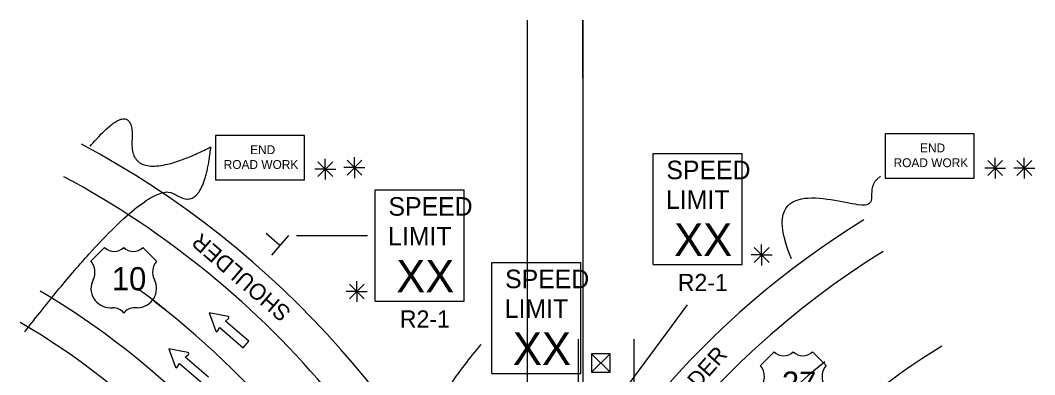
# Model space of a CAD drawing. Extents: x 16284 to 18474, y 5417 to 6974.
# Drawn here: x 16725.7 to 17163.1, y 6821.2 to 6974.1 of the extents above; entities that cross this region are included whole.
import ezdxf

# ---------------------------------------------------------------- set-up
doc = ezdxf.new("R2010")
doc.units = 0
for name, color, linetype in [('ALI_LEGAL_EX', 7, 'Continuous'), ('MT_SCRATCH_LEVEL_E', 7, 'Continuous'), ('PAVT_EDGE_EX', 7, 'Continuous'), ('TRAFFIC_SIGNS_PR', 7, 'Continuous'), ('TYPICAL_EX', 7, 'Continuous'), ('TYPICAL_TEXT_DIMEN_PR', 7, 'Continuous')]:
    doc.layers.add(name, color=color, linetype=linetype)

msp = doc.modelspace()

# ---------------------------------------------------------------- linework, layer by layer
at = {"layer": 'ALI_LEGAL_EX'}
for p, q in [((16944.3, 6974.12), (16944.3, 6155.98)), ((16968.3, 6974.12), (16968.3, 6155.98)), ((16966.29, 6836.53), (16966.29, 5997.6)), ((16990.29, 6836.53), (16990.29, 5997.6))]:
    msp.add_line(p, q, dxfattribs=at)
for points in [[(16968.3, 6949.12), (16968.3, 6974.12)], [(16790.41, 6847.41), (16783.31, 6852.89)]]:
    msp.add_lwpolyline(points, dxfattribs=at)
for centre, radius, start, end in [((16561.13, 6564.7), 364, 0, 53.7921), ((17289.13, 6564.7), 340, 129.5666, 180)]:
    msp.add_arc(centre, radius, start, end, dxfattribs=at)
at = {"layer": 'MT_SCRATCH_LEVEL_E'}
for p, q in [((16815.35, 6846.27), (16807.16, 6847.85)), ((16807.16, 6847.85), (16809.97, 6840.01)), ((16814.16, 6844.32), (16815.56, 6845.47)), ((16810.8, 6839.93), (16811.72, 6841.49)), ((16811.72, 6841.49), (16821.77, 6832.84)), ((16824.21, 6835.68), (16814.16, 6844.32)), ((16797.97, 6830.75), (16789.78, 6832.33)), ((16789.78, 6832.33), (16792.59, 6824.49)), ((16821.77, 6832.84), (16824.21, 6835.68)), ((16796.78, 6828.8), (16798.18, 6829.94)), ((16806.83, 6820.15), (16796.78, 6828.8)), ((16793.42, 6824.41), (16794.34, 6825.96)), ((16794.34, 6825.96), (16804.39, 6817.32))]:
    msp.add_line(p, q, dxfattribs=at)
for centre, start, end in [((16815.26, 6845.82), 309.3361, 79.073), ((16810.4, 6840.18), 199.7248, 329.2637), ((16797.88, 6830.29), 309.3361, 79.073), ((16793.02, 6824.65), 199.7248, 329.2637)]:
    msp.add_arc(centre, 0.463, start, end, dxfattribs=at)
at = {"layer": 'PAVT_EDGE_EX'}
for centre, radius, start, end in [((16561.13, 6564.7), 404, 21.0961, 61.7914), ((16561.13, 6564.7), 388, 17.512, 61.7914), ((17289.13, 6564.7), 380, 121.7103, 157.5011), ((17289.13, 6564.7), 364, 121.7103, 165.0045), ((16561.13, 6564.7), 340, 0, 59.3698), ((16561.13, 6564.7), 324, 0, 59.47), ((17289.13, 6564.7), 316, 121.7103, 180)]:
    msp.add_arc(centre, radius, start, end, dxfattribs=at)
at = {"layer": 'TRAFFIC_SIGNS_PR'}
for p, q in [((16998.53, 6916.68), (17036.93, 6916.68)), ((16998.53, 6868.68), (16998.53, 6916.68)), ((17036.93, 6868.68), (17036.93, 6916.68)), ((16878.7, 6900.93), (16917.1, 6900.93)), ((16878.7, 6852.93), (16878.7, 6900.93)), ((16917.1, 6852.93), (16917.1, 6900.93)), ((16928.99, 6869.65), (16967.39, 6869.65)), ((16928.99, 6821.65), (16928.99, 6869.65)), ((16967.39, 6821.65), (16967.39, 6869.65)), ((16998.53, 6868.68), (17036.93, 6868.68)), ((16878.7, 6852.93), (16917.1, 6852.93)), ((16928.99, 6821.65), (16967.39, 6821.65))]:
    msp.add_line(p, q, dxfattribs=at)
for points in [[(16809.82, 6905.22), (16848.22, 6905.22), (16848.22, 6924.42), (16809.82, 6924.42)], [(17098.64, 6905.99), (17137.04, 6905.99), (17137.04, 6925.19), (17098.64, 6925.19)]]:
    msp.add_lwpolyline(points, close=True, dxfattribs=at)
at = {"layer": 'TYPICAL_EX'}
for p, q in [((16756.18, 6870.17), (16762.08, 6876.06)), ((16784.48, 6870.17), (16778.59, 6876.06)), ((16764.43, 6850.11), (16765.61, 6850.11)), ((16776.24, 6850.11), (16775.06, 6850.11)), ((17044.83, 6825.12), (17050.72, 6831.02)), ((17073.13, 6825.12), (17067.23, 6831.02))]:
    msp.add_line(p, q, dxfattribs=at)
for centre, radius, start, end in [((16766.21, 6880.36), 5.96, 226.1404, 313.8596), ((16774.46, 6880.36), 5.96, 226.1404, 313.8596), ((16750.6, 6865.45), 7.31, 333.0977, 40.1936), ((16790.07, 6865.45), 7.31, 139.8064, 206.9023), ((16764.44, 6858.35), 8.24, 152.6698, 269.9013), ((16776.22, 6858.35), 8.24, 270.0987, 27.3302), ((16765.62, 6844.2), 5.91, 37.1038, 90.1385), ((16775.04, 6844.2), 5.91, 89.8615, 142.8962), ((17054.85, 6835.31), 5.96, 226.1404, 313.8596), ((17063.11, 6835.31), 5.96, 226.1404, 313.8596), ((17039.24, 6820.4), 7.31, 333.0977, 40.1936), ((17078.72, 6820.4), 7.31, 139.8064, 206.9023)]:
    msp.add_arc(centre, radius, start, end, dxfattribs=at)
at = {"layer": 'TYPICAL_TEXT_DIMEN_PR'}
for p, q in [((16869.8, 6910.53), (16869.8, 6914.99)), ((16854.06, 6913.1), (16860.43, 6906.72)), ((16860.43, 6913.1), (16854.06, 6906.72)), ((16857.24, 6909.91), (16857.24, 6914.36)), ((16866.61, 6913.72), (16872.99, 6907.35)), ((16872.99, 6913.72), (16866.61, 6907.35)), ((17142.88, 6913.56), (17149.25, 6907.18)), ((17149.25, 6913.56), (17142.88, 6907.18)), ((17146.07, 6910.37), (17146.07, 6914.82)), ((17161.81, 6913.56), (17155.43, 6907.18)), ((17155.44, 6913.56), (17161.81, 6907.18)), ((17158.62, 6910.37), (17158.62, 6914.82)), ((16857.24, 6909.91), (16852.71, 6909.91)), ((16857.24, 6909.91), (16860.43, 6909.91)), ((16857.24, 6909.91), (16861.72, 6909.91)), ((16857.24, 6909.91), (16857.24, 6905.41)), ((16869.8, 6910.53), (16865.27, 6910.53)), ((16869.8, 6910.53), (16872.99, 6910.53)), ((16869.8, 6910.53), (16874.28, 6910.53)), ((16869.8, 6910.53), (16869.8, 6906.03)), ((17146.07, 6910.37), (17141.53, 6910.37)), ((17146.07, 6910.37), (17149.25, 6910.37)), ((17146.07, 6910.37), (17150.54, 6910.37)), ((17146.07, 6910.37), (17146.07, 6905.87)), ((17158.62, 6910.37), (17154.09, 6910.37)), ((17158.62, 6910.37), (17161.81, 6910.37)), ((17158.62, 6910.37), (17163.1, 6910.37)), ((17158.62, 6910.37), (17158.62, 6905.87)), ((16837.65, 6876.99), (16831.75, 6882.07)), ((16841.32, 6881.26), (16833.98, 6872.73)), ((16844.86, 6881.26), (16875.44, 6881.26)), ((17042.16, 6876.04), (17048.54, 6869.67)), ((17048.54, 6876.04), (17042.16, 6869.67)), ((17045.35, 6872.86), (17045.35, 6877.31)), ((17045.35, 6872.86), (17040.82, 6872.86)), ((17045.35, 6872.86), (17048.54, 6872.86)), ((17045.35, 6872.86), (17049.83, 6872.86)), ((17045.35, 6872.86), (17045.35, 6868.36)), ((16867.6, 6860.28), (16873.97, 6853.9)), ((16873.97, 6860.28), (16867.6, 6853.9)), ((16870.78, 6857.09), (16870.78, 6861.55)), ((16870.78, 6857.09), (16866.25, 6857.09)), ((16870.78, 6857.09), (16873.97, 6857.09)), ((16870.78, 6857.09), (16875.26, 6857.09)), ((16870.78, 6857.09), (16870.78, 6852.59)), ((16957.13, 6775.18), (17013.42, 6851.3)), ((16972, 6822.26), (16980, 6830.26)), ((16972, 6830.25), (16980, 6822.26))]:
    msp.add_line(p, q, dxfattribs=at)
msp.add_lwpolyline([(16972, 6830.25), (16972, 6822.26), (16980, 6822.26), (16980, 6830.26)], close=True, dxfattribs=at)
for points, degree in [([(16755.84, 6919.73), (16775.05, 6942.33), (16772.72, 6901.72), (16807.9, 6919.45)], 2), ([(16727.62, 6839.68), (16780.55, 6907.8), (16804.75, 6890.22), (16807.9, 6919.45)], 2), ([(17058.28, 6871.13), (17043.1, 6907.35), (17107.34, 6885.02), (17088.67, 6901.32), (17096.57, 6906.83)], 3), ([(16909.99, 6783.05), (16925.05, 6790.93), (16915.89, 6798.15), (16900.83, 6806.02), (16924.4, 6834.24)], 2)]:
    msp.add_open_spline(points, degree=degree, dxfattribs=at)

# ---------------------------------------------------------------- texts
at = {"layer": 'TRAFFIC_SIGNS_PR'}
for s, height, p in [('END', 3.831, (16824.82, 6916.35)), ('END', 3.831, (17113.65, 6917.12)), ('ROAD WORK', 3.831, (16813.43, 6909.97)), ('SPEED', 8, (17004.3, 6905.54)), ('ROAD WORK', 3.831, (17102.26, 6910.74)), ('SPEED', 8, (16884.47, 6889.8)), ('LIMIT', 8, (17004.14, 6892.74)), ('LIMIT', 8, (16884.31, 6876.99)), ('XX', 14.031, (17007.64, 6872.43)), ('XX', 14.031, (16887.82, 6856.69)), ('SPEED', 8, (16934.76, 6858.52)), ('R2-1', 7.44, (17009.21, 6857.24)), ('LIMIT', 8, (16934.6, 6845.72)), ('R2-1', 7.44, (16889.38, 6841.49)), ('XX', 14.031, (16938.11, 6825.41))]:
    msp.add_text(s, height=height, dxfattribs=at).set_placement(p)
at = {"layer": 'TYPICAL_EX'}
for s, p in [('10', (16765.18, 6857.6)), ('27', (17054.09, 6812.55))]:
    msp.add_text(s, height=10, dxfattribs=at).set_placement(p)
at = {"layer": 'TYPICAL_TEXT_DIMEN_PR'}
for rotation, p in [(139.2839, (16842.95, 6848.81)), (48.378, (16996.49, 6790.64))]:
    msp.add_text('SHOULDER', height=7, rotation=rotation, dxfattribs=at).set_placement(p)

doc.saveas('drawing.dxf')
